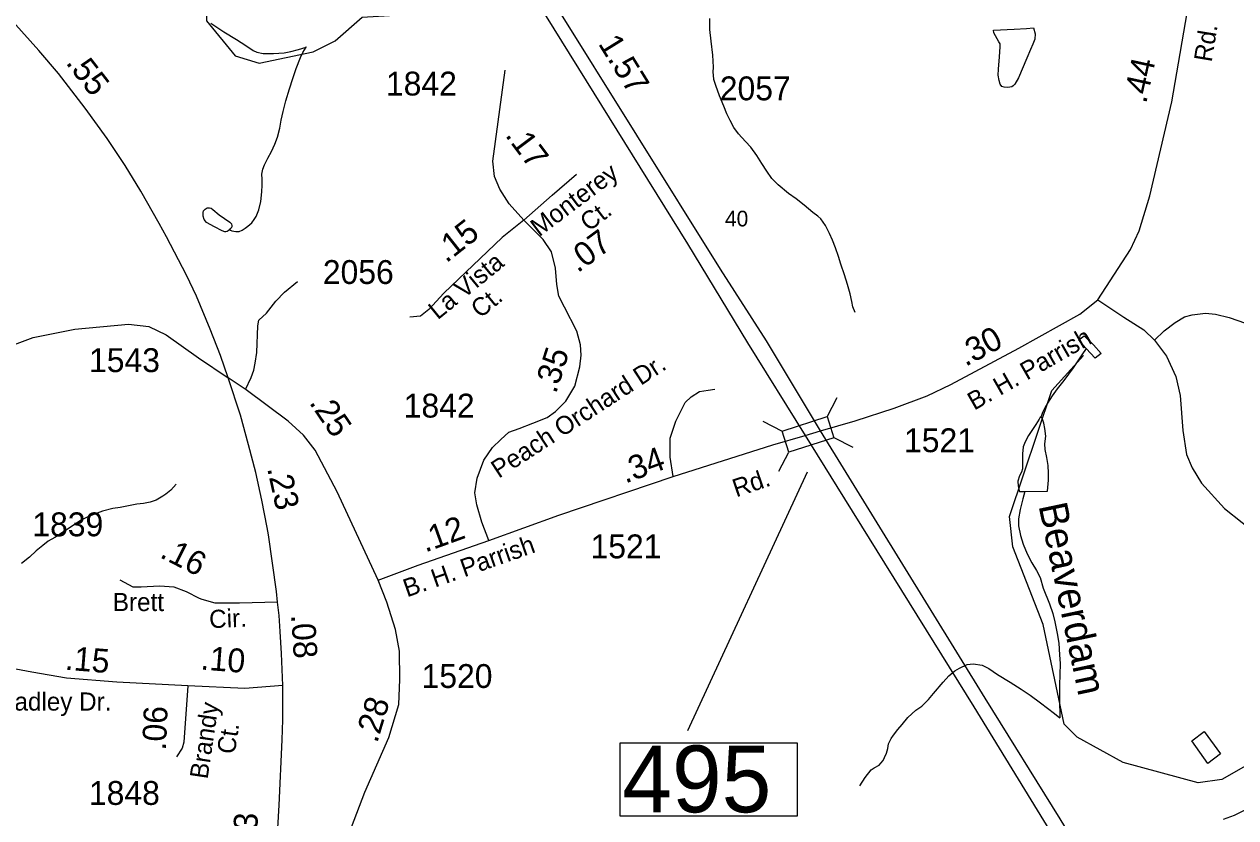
# Model space of a CAD drawing. Extents: x 2082433 to 2279600, y 546599 to 755198.
# Drawn here: x 2124031 to 2130383, y 646888 to 651046 of the extents above; entities that cross this region are included whole.
import ezdxf

# ---------------------------------------------------------------- set-up
doc = ezdxf.new("R2010")
doc.units = 0
for name, color, linetype in [('Exist Hydrographic Creek Single Shore', 7, 'Continuous'), ('Exist Hydrographic Creek Single Shore Label', 7, 'Continuous'), ('Exist Hydrographic Misc Water Feature', 7, 'Continuous'), ('Exist Road Non-System Type 51', 7, 'Continuous'), ('Exist Road Primary Interstate Divided Center Attributed', 7, 'Continuous'), ('Exist Road Primary Interstate Mileage Hundredths English Label', 7, 'Continuous'), ('Exist Road Primary Interstate Shield CELL', 7, 'Continuous'), ('Exist Road Primary NC Attributed', 7, 'Continuous'), ('Exist Road Primary NC Service Mileage Hundredths English Label', 7, 'Continuous'), ('Exist Road Secondary Mileage Hundredths English Label', 7, 'Continuous'), ('Exist Road Secondary Structure Standard Bridge CELL', 7, 'Continuous'), ('Exist Road Secondary Structure Standard Bridge Number Label', 7, 'Continuous'), ('Exist Road Secondary Type 51 Attributed', 7, 'Continuous'), ('Exist Road Secondary Type 51 Label', 7, 'Continuous'), ('Exist Road Secondary Type 51 Number Label', 7, 'Continuous')]:
    doc.layers.add(name, color=color, linetype=linetype)

msp = doc.modelspace()

# ---------------------------------------------------------------- linework, layer by layer
at = {"layer": 'Exist Hydrographic Creek Single Shore'}
for points in [[(2125017.1, 651696.6), (2125018.1, 651430.9), (2124993.1, 651388.7), (2124986.1, 651064.1), (2125137, 650880.6), (2125262.1, 650842), (2125545.1, 650901.9), (2125660.9, 650958.5), (2125803, 651083.6), (2126577.1, 651130.2), (2126744, 651172.8), (2127643, 651184), (2127743, 651244.2), (2127966.1, 651620.2), (2127966.1, 651712.1), (2128024, 651802.8), (2128074, 651818.2)], [(2130650.8, 647281.4), (2130309.8, 647088.3), (2130186, 647071.2), (2129792.9, 647177.5), (2129550.9, 647310.4), (2129483.9, 647377.3), (2129374, 647901.2), (2129214, 648307.9), (2129196, 648465.8), (2129418.9, 649127.2), (2129584, 649310.8)]]:
    msp.add_lwpolyline(points, dxfattribs=at)
at = {"layer": 'Exist Hydrographic Misc Water Feature'}
for points in [[(2128387.9, 649534.8), (2128375.4, 649564.7), (2128369.5, 649592.7), (2128361.3, 649632.5), (2128347.1, 649682.5), (2128331.1, 649732.4), (2128312.9, 649788.3), (2128300.8, 649828.2), (2128284.2, 649874.1), (2128268.4, 649913.9), (2128252.2, 649949.9), (2128232.1, 649991.9), (2128207.9, 650025.6), (2128191.5, 650039.8), (2128165.4, 650059.6), (2128119.5, 650097.4), (2128077.5, 650131.3), (2128037.1, 650158.9), (2127983.2, 650204.8), (2127951, 650238.5), (2127924.9, 650276.5), (2127898.9, 650316.1), (2127872.2, 650358.3), (2127840, 650402.1), (2127812.3, 650431.8), (2127776.1, 650471.8), (2127751.9, 650505.4), (2127732, 650541.3), (2127715.4, 650577.5), (2127699.6, 650617.2), (2127675.4, 650671.2), (2127657.1, 650725), (2127646.7, 650757), (2127644.8, 650779.2), (2127642.8, 650794.9), (2127644.6, 650821), (2127640.3, 650884.9), (2127631.9, 650956.8), (2127625.7, 651018.9), (2127625.5, 651077)], [(2125008.3, 651051.2), (2125076.7, 651005.6), (2125142.8, 650966), (2125192.6, 650934), (2125230.9, 650908.4), (2125250.8, 650900.5), (2125283.2, 650892.8), (2125307, 650892.8), (2125337.2, 650892.7), (2125393.1, 650897.2), (2125428.6, 650903.2), (2125469, 650913.3), (2125508.7, 650926.2), (2125510.8, 650929.7)], [(2129287.5, 650868.1), (2129244.2, 650765.9), (2129224.5, 650732), (2129216.3, 650723.9), (2129208.5, 650717.8), (2129188.4, 650713.9), (2129168.8, 650715.7), (2129156.7, 650719.6), (2129148.5, 650731.8), (2129142.3, 650751.7), (2129138, 650779.5), (2129138.4, 650811.6), (2129144, 650875.6), (2129147.4, 650927.8), (2129147.6, 650943.6), (2129141.5, 650953.4), (2129131.4, 650969.6), (2129115, 651001.3), (2129113.2, 651015.3), (2129221.1, 651020.1), (2129285, 651024.2), (2129323.2, 651028.2), (2129331.2, 650996.5), (2129329.3, 650968.4), (2129319.5, 650942.3), (2129305.9, 650914.4), (2129287.5, 650868.1)], [(2125106.9, 649968), (2125119, 649964.1), (2125129, 649962.2), (2125140.9, 649960.4), (2125157.1, 649960.4), (2125172.9, 649966.5), (2125188.7, 649976.7), (2125203.1, 649988.7), (2125223.2, 650004.7), (2125236.7, 650022.5), (2125246.7, 650038.5), (2125260.5, 650072.9), (2125270.3, 650116.9), (2125276.5, 650168.6), (2125277.9, 650202.9), (2125277.7, 650235), (2125275.6, 650260.9), (2125281.2, 650286.7), (2125289.6, 650308.6), (2125307, 650344.9), (2125327.1, 650378.8), (2125345, 650417), (2125358.5, 650455.1), (2125371, 650501.1), (2125378.4, 650543), (2125388.2, 650589.4), (2125402.2, 650645.2), (2125421.8, 650707.2), (2125439.3, 650761.3), (2125456.9, 650813.4), (2125479.1, 650871.7), (2125491, 650897.4), (2125508.7, 650926.2), (2125510.8, 650929.7)], [(2125106.9, 649968), (2125100.7, 649964), (2125095, 649960), (2125087, 649958), (2125082.9, 649958.3), (2125069, 649964), (2125028.8, 649983.8), (2124986.9, 650007.6), (2124981, 650013.4), (2124974.6, 650023.7), (2124968.9, 650039.6), (2124968.7, 650059.4), (2124970.5, 650067.7), (2124978.5, 650077.4), (2124990.6, 650083.7), (2125002.5, 650083.5), (2125010.7, 650081.5), (2125018.7, 650075.9), (2125052.8, 650048), (2125108.9, 650008.2), (2125116.9, 650000.1), (2125119.2, 649990.1), (2125119, 649984), (2125115.1, 649978.1), (2125111, 649974.2), (2125106.9, 649968)], [(2129598.3, 649346), (2129594.5, 649350.2), (2129560.2, 649391.9), (2129588.5, 649413.9), (2129636.3, 649366.2), (2129676.7, 649320.3), (2129646.7, 649296.4), (2129598.3, 649346)], [(2129598.3, 649346), (2129576.4, 649314), (2129530.7, 649245.9), (2129481.5, 649179.5), (2129447.4, 649135.6), (2129419.5, 649099.2), (2129395.8, 649061), (2129381.8, 649035.2), (2129370.1, 649011), (2129365.8, 649001.1), (2129361.7, 648987.1)], [(2129361.7, 648987.1), (2129358, 648987.3), (2129352.5, 648977.2), (2129334.2, 648949.1), (2129296.5, 648890.8), (2129278.5, 648857), (2129268.6, 648830.9), (2129264.7, 648794.9), (2129265.1, 648730.8), (2129265.3, 648716.6), (2129259.4, 648698.8), (2129249.1, 648678.9), (2129241.1, 648650.9), (2129242, 648624.9), (2129245.7, 648610.9), (2129247.7, 648600.9), (2129249.6, 648596.9), (2129277.6, 648596.7)], [(2129277.6, 648596.7), (2129395.8, 648599.5), (2129401.7, 648657.5), (2129401.3, 648693.6), (2129399.4, 648733.2), (2129392.9, 648775.2), (2129382.8, 648817.2), (2129382.6, 648847.3), (2129386.3, 648887.3), (2129382, 648927.3), (2129376.5, 648955.3), (2129368.1, 648981.3), (2129361.7, 648987.1)], [(2124827.2, 648635.4), (2124799.1, 648605.2), (2124772.9, 648583.2), (2124757.3, 648573), (2124721.6, 648552.8), (2124691.5, 648540.8), (2124655.2, 648534.5), (2124621.3, 648530.3), (2124585.4, 648524.4), (2124533.6, 648514), (2124495.6, 648508), (2124441.7, 648493.8), (2124389.4, 648475.4), (2124357.6, 648461.1), (2124325.8, 648445.2), (2124291.8, 648423.2), (2124246.1, 648392.8), (2124190.3, 648356.6), (2124156.3, 648336.7), (2124128.4, 648314.5), (2124092.7, 648286.3), (2124058.9, 648254.1), (2124017, 648219.8)], [(2129277.6, 648596.7), (2129265.8, 648558.8), (2129252.2, 648502.8), (2129244.6, 648454.9), (2129244.6, 648416.8), (2129254.7, 648367), (2129269, 648321), (2129289.1, 648270.9), (2129313.5, 648223), (2129337.5, 648183.3), (2129357.4, 648147.4), (2129374, 648091.4), (2129406.4, 648009.4), (2129424.5, 647957.6), (2129434.5, 647913.9), (2129447.2, 647854), (2129455, 647802.1), (2129459.5, 647741.8), (2129461.6, 647696.1), (2129460.1, 647635.9), (2129458.3, 647583.9), (2129458.5, 647531.9), (2129458.7, 647482), (2129460.6, 647439.9), (2129461, 647411.9)], [(2128412.5, 647055.4), (2128440.4, 647097.8), (2128470.6, 647137.9), (2128486.6, 647149.7), (2128512.4, 647164), (2128522, 647173.9), (2128534.1, 647187.9), (2128541.9, 647204.1), (2128552, 647226.2), (2128558.1, 647250), (2128561.6, 647274.2), (2128568, 647286.2), (2128575.8, 647302.1), (2128587.6, 647320.2), (2128611.2, 647350.2), (2128633.6, 647376.4), (2128662.9, 647412.6), (2128704.9, 647450.8), (2128736.7, 647472.8), (2128772.6, 647507.1), (2128798.4, 647539.3), (2128848.5, 647597.4), (2128878.4, 647631.4), (2128910, 647657.5), (2128934, 647671.7), (2128974, 647690), (2129005.7, 647694.1), (2129053.9, 647688), (2129088, 647670.3), (2129133.7, 647638.6), (2129200.1, 647599), (2129258.6, 647560.9), (2129304.7, 647529.2), (2129358.8, 647489.8), (2129432.9, 647434), (2129461, 647411.9)], [(2130235.9, 647171.3), (2130153.4, 647291.3), (2130217, 647339.3), (2130303.7, 647221.9), (2130235.9, 647171.3)]]:
    msp.add_lwpolyline(points, dxfattribs=at)
at = {"layer": 'Exist Road Non-System Type 51'}
for points in [[(2125190.3, 649132.6), (2125219.9, 649194.8), (2125233.6, 649233.3), (2125242.2, 649270.5), (2125249.7, 649325), (2125254.6, 649466.3), (2125261.5, 649495.4), (2125300.5, 649532), (2125350.1, 649595.2), (2125395.9, 649642.3), (2125462.9, 649698.1)], [(2129956.6, 649390.4), (2130008.3, 649439.6), (2130065.3, 649482.7), (2130113.6, 649512), (2130155, 649522.4), (2130224, 649532.7), (2130277.4, 649527.5), (2130348.2, 649508.6), (2130555.2, 649437.8), (2130831.2, 649350.7), (2131122.7, 649253.3), (2131336.6, 649182.5)], [(2127433.5, 648675.5), (2127416.6, 648778), (2127416.6, 648877.7), (2127447.5, 648966.2), (2127496.7, 649063.2), (2127527.6, 649094.1), (2127571.1, 649120.8), (2127617.5, 649129.2), (2127651.2, 649133.4)], [(2130618.8, 646995.1), (2130543.1, 646977.7), (2130482.1, 646954.4), (2130374.5, 646899.2), (2130316.3, 646878.8)]]:
    msp.add_lwpolyline(points, dxfattribs=at)
at = {"layer": 'Exist Road Primary Interstate Divided Center Attributed'}
for points in [[(2125101, 656322.4), (2125024.2, 656126.3), (2124962, 655968.5), (2124910.1, 655781.7), (2124862.3, 655563.8), (2124833.3, 655374.9), (2124828, 655244.1), (2124816.7, 655028.2), (2124827.1, 654895.4), (2124870.6, 654507.2), (2124926.7, 654285.1), (2125015.9, 654017.3), (2125096.9, 653820.2), (2125175.8, 653666.5), (2125353.2, 653369.4), (2125702.8, 652816.1), (2126026.8, 652290.3), (2126459.2, 651579.4), (2126726.2, 651152), (2127508.6, 649894.7), (2127823.3, 649376.4), (2128125.3, 648890.4)], [(2128205.4, 648915.7), (2127922.6, 649387.5), (2127681.4, 649762.7), (2126803.4, 651167.7), (2126530.8, 651605.2), (2126043.4, 652414.9), (2125377.1, 653477.7), (2125198.6, 653789), (2125103.1, 653998.7), (2125020.1, 654233.2), (2124943.3, 654509.3), (2124908, 654764.6), (2124897.6, 654988.8), (2124897.6, 655200.5), (2124916.3, 655443.4), (2124966.1, 655700.8), (2125013.9, 655868.9), (2125077.2, 656048.4), (2125161.2, 656261.2)], [(2131151.7, 644142.6), (2131067.4, 644280.2), (2130803.3, 644712.9), (2130283.6, 645558.5), (2129859.4, 646232.7), (2129461.8, 646881.7), (2129068.5, 647513.8), (2128205.4, 648915.7)], [(2128125.3, 648890.4), (2128290.8, 648624.1), (2129009.5, 647468.9), (2129408.5, 646819.9), (2129797.6, 646193.4), (2130244.2, 645457.4), (2130749.9, 644651.1), (2130931.6, 644359.6)]]:
    msp.add_lwpolyline(points, dxfattribs=at)
at = {"layer": 'Exist Road Primary NC Attributed'}
for points in [[(2125100.6, 649192.8), (2125059, 649309.6), (2125005.7, 649447.8), (2124933.4, 649620.6), (2124880.6, 649731.6), (2124777, 649932), (2124738.5, 650002.4), (2124642.6, 650170.7), (2124560.1, 650306.6), (2124465.9, 650447.1), (2124349.2, 650606.9), (2124209.5, 650787.6), (2124107.1, 650908), (2123970.1, 651061.3), (2123849.2, 651194.8), (2123700.8, 651357.3), (2123488, 651592)], [(2125359, 648016.6), (2125353.5, 648073.7), (2125311.4, 648370.1), (2125303.9, 648408.7), (2125276.2, 648552.2), (2125244.3, 648696.8), (2125207, 648842.6), (2125163.9, 648997.6), (2125100.6, 649192.8)], [(2125386.2, 647579.9), (2125380.1, 647748.1), (2125372.7, 647864), (2125367.3, 647946.7), (2125359, 648016.6)], [(2125309.2, 645843.1), (2125319.4, 646041.9), (2125324.7, 646155.2), (2125329, 646240), (2125336.4, 646382.5), (2125345.5, 646561.7), (2125347.6, 646623.4), (2125355, 646742.5), (2125366.7, 646952.9), (2125382.2, 647296.8), (2125386.5, 647401.4), (2125386.2, 647579.9)]]:
    msp.add_lwpolyline(points, dxfattribs=at)
at = {"layer": 'Exist Road Secondary Structure Standard Bridge CELL'}
for p, q in [((2128240.5, 648989.1), (2128292.4, 649089.6)), ((2127903.6, 648966), (2128004.2, 648914.2)), ((2128274.9, 648881.2), (2128375.5, 648829.4)), ((2127987.5, 648703.3), (2128039.4, 648803.9))]:
    msp.add_line(p, q, dxfattribs=at)
msp.add_lwpolyline([(2128004.2, 648914.2), (2128240.3, 648989.6), (2128275.5, 648879.3), (2128039.4, 648803.9)], close=True, dxfattribs=at)
at = {"layer": 'Exist Road Secondary Structure Standard Bridge Number Label'}
msp.add_line((2128134.9, 648698.3), (2127508.8, 647343), dxfattribs=at)
msp.add_lwpolyline([(2127154.4, 647280.5), (2128083.4, 647280.5), (2128083.4, 646896.4), (2127154.4, 646896.4)], close=True, dxfattribs=at)
at = {"layer": 'Exist Road Secondary Type 51 Attributed'}
for points in [[(2129659.9, 649602.6), (2129830.7, 649866.5), (2129877.2, 649963.1), (2129932.4, 650147.7), (2130048, 650639.3), (2130146.3, 651208.5), (2130166.9, 651440.3), (2130200.4, 651664.9), (2130239.5, 651839)], [(2126649.3, 650019.6), (2126572.9, 650105.1), (2126524.1, 650181.4), (2126496.6, 650248.6), (2126487.4, 650328), (2126553.1, 650805.8)], [(2126649.3, 650019.6), (2126798.9, 650150.9), (2126927.1, 650260.8)], [(2126649.3, 650019.6), (2126535.9, 649928.4), (2126231.1, 649636.3), (2126152.4, 649550.6), (2126107.5, 649516.9), (2126052.7, 649511.3)], [(2126467.1, 648339.8), (2126430.5, 648436.7), (2126403.9, 648528), (2126394, 648591.2), (2126405.3, 648667), (2126441, 648762), (2126486.5, 648827.6), (2126529.3, 648869.4), (2126571, 648908.7), (2126625.8, 648926.9), (2126697.4, 648955), (2126771.9, 648985.9), (2126816.1, 649016.8), (2126869.5, 649071.6), (2126917.3, 649148.9), (2126944, 649250), (2126951, 649311.8), (2126946.8, 649365.2), (2126928.5, 649438.2), (2126863.2, 649563.2), (2126833.7, 649620.8), (2126822.4, 649682.6), (2126816.8, 649768.3), (2126794.4, 649852.6), (2126750.8, 649917.2), (2126649.3, 650019.6)], [(2128205.4, 648915.7), (2128388, 648967.6), (2128592.5, 649033.3), (2128764.8, 649099.5), (2128889.2, 649158.4), (2129245.6, 649347.9), (2129565.4, 649526.3), (2129659.9, 649602.6)], [(2129659.9, 649602.6), (2129796.2, 649510.3), (2129901.4, 649443.9), (2129956.6, 649390.4), (2130020.4, 649305.9), (2130068.7, 649200.6), (2130091.1, 649100.6), (2130104.9, 648916.9), (2130123.9, 648791.8), (2130155, 648721.1), (2130203.3, 648641.7), (2130324, 648508.9), (2130788, 648141.5)], [(2123837.4, 649315.4), (2124077.7, 649404.5), (2124295.7, 649447.5), (2124576.6, 649474.6), (2124683.2, 649461.9), (2124775.5, 649418.9), (2124943.8, 649298.2), (2125100.6, 649192.8)], [(2125887.2, 648132.9), (2125672, 648595.4), (2125556.8, 648814.5), (2125495, 648891.8), (2125413.6, 648966.2), (2125193.9, 649130.2), (2125100.6, 649192.8)], [(2128125.3, 648890.4), (2128205.4, 648915.7)], [(2126467.1, 648339.8), (2126834.4, 648473.7), (2127433.5, 648675.5), (2127955.5, 648841.5), (2128125.3, 648890.4)], [(2125887.2, 648132.9), (2126095.3, 648211), (2126467.1, 648339.8)], [(2125359, 648016.6), (2125159.5, 648011.8), (2125031.5, 648011.8), (2124963.3, 648030.9), (2124949.7, 648036.4), (2124881.6, 648071.8), (2124816.2, 648096.4), (2124739.9, 648101.8), (2124644.5, 648096.4), (2124600.9, 648096.4), (2124534, 648133)], [(2125704.6, 646727.6), (2125816.4, 647022.2), (2125942.5, 647308.9), (2125995, 647481.6), (2126000.2, 647613), (2125998.6, 647760.3), (2125977.5, 647875), (2125932.2, 648016.7), (2125887.2, 648132.9)], [(2124887.7, 647579.7), (2124515.8, 647598.3), (2124251.8, 647619.3), (2124070.8, 647650.3), (2123959.3, 647671.4), (2123918.4, 647673.9), (2123863.8, 647661.5)], [(2124887.7, 647579.7), (2124866.6, 647283.4), (2124859.2, 647252.4), (2124828.2, 647206.5)], [(2125386.2, 647579.9), (2125186.8, 647564.6), (2124887.7, 647579.7)]]:
    msp.add_lwpolyline(points, dxfattribs=at)

# ---------------------------------------------------------------- texts
at = {"layer": 'Exist Hydrographic Creek Single Shore Label'}
msp.add_text('Beaverdam', height=150, rotation=281.8974, dxfattribs=at).set_placement((2129348.2, 648523.4))
at = {"layer": 'Exist Road Primary Interstate Mileage Hundredths English Label'}
msp.add_text('1.57', height=125, rotation=301.71379, dxfattribs=at).set_placement((2127037.5, 650944.2))
at = {"layer": 'Exist Road Primary Interstate Shield CELL'}
msp.add_text('40', height=82.02, dxfattribs=at).set_placement((2127704.9, 649986.7))
at = {"layer": 'Exist Road Primary NC Service Mileage Hundredths English Label'}
for s, rotation, p in [('.55', 307.71709, (2124245.1, 650843.7)), ('.23', 282.44072, (2125303.5, 648718.6)), ('.08', 273.64749, (2125429.8, 647950.5)), ('.33', 87.42685, (2125246.1, 646679.4))]:
    msp.add_text(s, height=125, rotation=rotation, dxfattribs=at).set_placement(p)
at = {"layer": 'Exist Road Secondary Mileage Hundredths English Label'}
for s, rotation, p in [('.44', 77.67839, (2129912.9, 650626.9)), ('.17', 306.82846, (2126548.8, 650463.7)), ('.15', 38.39328, (2126243.3, 649791.8)), ('.07', 36.36975, (2126932.4, 649740.2)), ('.30', 27.99623, (2128965.9, 649250.1)), ('.35', 72.25088, (2126818.8, 649106.3)), ('.25', 304.24046, (2125521.6, 649062.9)), ('.34', 20.23799, (2127182.2, 648638.3)), ('.12', 19.91767, (2126133.2, 648277)), ('.16', 333.22952, (2124736.1, 648254.7)), ('.15', 355.45693, (2124241.4, 647663.7)), ('.10', 355.46798, (2124952.7, 647664.8)), ('.28', 73.09439, (2125880.8, 647275.1)), ('.06', 87.62801, (2124773.3, 647238.5))]:
    msp.add_text(s, height=125, rotation=rotation, dxfattribs=at).set_placement(p)
at = {"layer": 'Exist Road Secondary Structure Standard Bridge Number Label'}
msp.add_text('495', height=350, dxfattribs=at).set_placement((2127166.9, 646916.2))
at = {"layer": 'Exist Road Secondary Type 51 Label'}
for s, rotation, p in [('Rd.', 80.69431, (2130256.5, 650844.6)), ('Monterey', 37.01248, (2126730.9, 649929.9)), (' Ct.', 37.01248, (2126962.3, 649935.3)), ('La Vista', 39.19125, (2126198.6, 649494)), (' Ct.', 39.19125, (2126394, 649479.2)), ('B. H. Parrish', 29.7565, (2129011.6, 649020.5)), ('Peach Orchard Dr.', 33.16637, (2126518.7, 648663.7)), ('Rd.', 18.83334, (2127763.7, 648566)), ('B. H. Parrish', 19.34934, (2126037.7, 648042.2)), ('Cir.', 2.43208, (2125002.1, 647880.7)), ('Brandy', 81.53604, (2124991.7, 647087)), (' Ct.', 81.53604, (2125129.2, 647182.3))]:
    msp.add_text(s, height=95, rotation=rotation, dxfattribs=at).set_placement(p)
for s, p in [('Brett', (2124495.2, 647970.8)), ('Bradley Dr.', (2123852.4, 647449.2))]:
    msp.add_text(s, height=95, dxfattribs=at).set_placement(p)
at = {"layer": 'Exist Road Secondary Type 51 Number Label'}
for s, p in [('1842', (2125927.2, 650672.7)), ('2057', (2127677.6, 650647.6)), ('2056', (2125596.2, 649685)), ('1543', (2124370.3, 649223.2)), ('1543', (2124370.3, 649223.2)), ('1842', (2126020.4, 648984.9)), ('1521', (2128643.7, 648803.4)), ('1839', (2124073.2, 648362.7)), ('1521', (2126999.9, 648247.3)), ('1520', (2126114, 647567.8)), ('1848', (2124369.8, 646955))]:
    msp.add_text(s, height=125, dxfattribs=at).set_placement(p)

doc.saveas('drawing.dxf')
